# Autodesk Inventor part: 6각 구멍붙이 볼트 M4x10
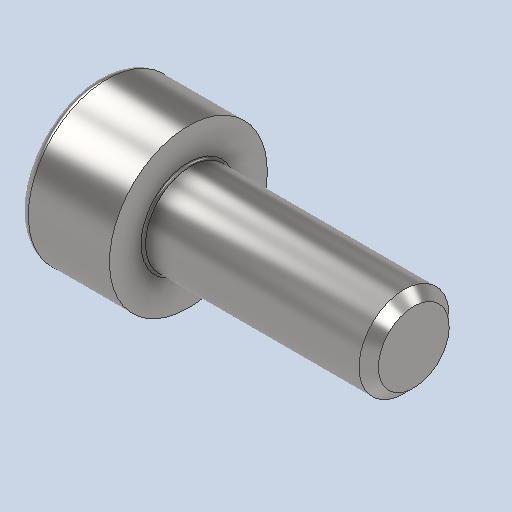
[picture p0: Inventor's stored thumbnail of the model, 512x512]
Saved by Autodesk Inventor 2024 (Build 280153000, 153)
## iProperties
Created: 2025-11
Part Number: 6각 구멍붙이 볼트 M4x10
Material: 강철, 연강
Description: 6각머리 태핑 나사
Document SubType Name: Modeling
Designer: Eud07
Density: 7.85 g/cm^3
Appearance: 기본값
Author: jhkim
Sending System: Autodesk Inventor 2026
Preprocessor: ST-DEVELOPER v20.1
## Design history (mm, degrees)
node "6각 구멍붙이 볼트 M4x101"
node "솔리드1"
body "Solid1"
